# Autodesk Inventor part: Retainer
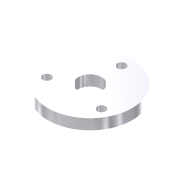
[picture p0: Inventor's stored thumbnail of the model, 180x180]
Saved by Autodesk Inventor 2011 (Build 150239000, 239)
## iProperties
Shininess: 77.0
Length Units: 11269
Angle Units: 11279
Time Units: 11290
Mass Units: 11283
Length Display Precision: 3
Angle Display Precision: 2
Created: 2002-01
Part Number: Retainer
Document SubType Name: Modeling
Designer: ***
Density: 1 g/cm^3
Density: 0.0
Volumn: 0.0
Area: 0.0
PropertySet Name: Model Information
Control State: 0
Master: False
Checked Out: False
Author: ***
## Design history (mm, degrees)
sketch "Sketch2"
  geometry: C1 r 100 at (0, 0); C2 r 28 at (0, 0)
  constraints: 2 centre point, 1 coincident
  dimensions: "d10" = 200 diameter of C1; "d11" = 56 diameter of C2
extrude "Extrusion2" new body sketch "Sketch2" stored distance "d12" = 25; taper "d13" = 0 deg
sketch "Sketch3"
  geometry: C1 r 28 at (0, 0) reference; 1 further point
  dimensions: "d14" = 75 distance of C1.centre point (0, 75)
hole "Hole1" sketch "Sketch3" at (0, 75) diameter "d15" = 20.3; stored, may be unused: countersink angle "d19" = 82 deg, drill point angle "d21" = 118 deg; dims "d16" = 6, "d17" = 4, "d18" = 2, "d20" = 8
pattern_circular "Circular Pattern1" dims angle "d24" = 360 deg
body "Solid1"
